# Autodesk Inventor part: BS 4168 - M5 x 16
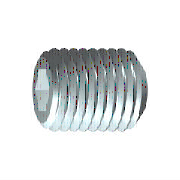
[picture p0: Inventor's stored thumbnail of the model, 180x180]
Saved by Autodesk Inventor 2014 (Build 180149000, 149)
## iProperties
IsCustomPart: 0
Created: 2008-01
Part Number: BS 4168 - M5 x 16
Material: Steel, Mild
Description: Hexagon socket screws and wrench keys, metric series- Specification for hexagon set screws with flat point
Document SubType Name: Modeling
Standard: BS 4168
Designer: latalom
Standards Organization: BSI
Language: en-US
Size Designation: M5 x 16
Categories: <MemberInstance><Categories><Category DisplayName="Fasteners" InternalName="e4da775c-781d-43d5-af7c-5136215cf5a6" Mnemonic="FSTN"><Category DisplayName="Bolts"
Density: 7.86 g/cm^3
Mass: 2.29997 g
Surface Area: 3.08393 cm^2
Volume: 0.292617 cm^3
Appearance: Steel
Author: latalom
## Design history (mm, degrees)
sketch "Sketch1"
  geometry: L1 (0, 0)-(12.167, 0); L2 (16, 1.443)-(16, 2.5); L3 (16, 2.5)-(0, 2.5); L4 (16, 1.443)-(13, 1.443); L5 (13, 1.443)-(12.167, 0); L6 (0, -0.5)-(0, 3) reference; L7 (0, 2.5)-(0, 0)
  constraints: 13 end point, 3 parallel, 1 collinear, 1 perpendicular, 1 point on line
  dimensions: "d0" = 3 distance of L2.start L4.end (= INTI); "d1" = 60 deg angle of L5 L1; "d2" = 5 diameter of L3 L1 (= NND); "d3" = 2.88675 diameter of L4 L1 (= 1.1547 x SW); "d5" = 16 distance from line of L2 L3.end (= NLG)
revolve "Body" sketch "Sketch1" stored, may be unused: angle "d6" = 90 deg
sketch "Sketch2"
  geometry: L1 (-0.722, 1.25)-(0.722, 1.25); L2 (0.722, 1.25)-(1.443, 0); L3 (1.443, 0)-(0.722, -1.25); L4 (0.722, -1.25)-(-0.722, -1.25); L5 (-0.722, -1.25)-(-1.443, 0); L6 (-1.443, 0)-(-0.722, 1.25); A1 r 1.443 centre (0, 0) between (-0.722, 1.25) and (0.722, 1.25) reference; 2 further points
  constraints: 12 end point, 2 point on circle, 1 coincident, 1 horizontal, 11 other
extrude "Slot" join sketch "Sketch2" taper "d9" = 0 deg; stored distance "d21" = 10
workaxis "Work Axis1"
workplane "Work Plane1"
body "Solid1"
chamfer "Chamfer1" distance "d7" = 0.49076 (= -0.5 x GD1 + 0.5 x NND); stored, may be unused: angle "d8" = 45 deg (= FAWI), second distance "d29" = 0.49076 (= -0.5 x GD1 + 0.5 x NND)
feature "Thread" dims "d11" = 16 (= NLG), "d12" = 0
chamfer "Chamfer2" distance "d13" = 0.49076 (= -0.5 x GD1 + 0.5 x NND); stored, may be unused: angle "d14" = 45 deg (= FAWI), second distance "d30" = 0.49076 (= -0.5 x GD1 + 0.5 x NND)
other parameters: "NND" = 5 [user parameter; used in 5 equation terms], "NLG" = 16 [user parameter; used in 2 equation terms], "INTI" = 3 [user parameter; used in 1 equation term], "FAWI" = 45 deg [user parameter; used in 2 equation terms], "SW" = 2.5 [user parameter; used in 2 equation terms], "GD1" = 4.01848 (= THREADDIA - 1.2269 x PTC) [user parameter; used in 4 equation terms], "d4" = 0, "FAWI1" = 45 deg [user parameter], "d15" = 0, "d31" = 0, "GUL" = 0.49076 (= 0.61345 x PTC) [user parameter], "SPD" = 3.5 [user parameter], "TPU" = 12.5 (computed from PTC) [user parameter], "TOA" = 30 deg [user parameter], "THREADDIA" = 5 [user parameter; used in 1 equation term], "PTC" = 0.8 [user parameter; used in 4 equation terms], "GAL" = 0.49076 (= 0.61345 x PTC) [user parameter], "E0" = 2.8875 (= 1.155 x SW) [user parameter]
